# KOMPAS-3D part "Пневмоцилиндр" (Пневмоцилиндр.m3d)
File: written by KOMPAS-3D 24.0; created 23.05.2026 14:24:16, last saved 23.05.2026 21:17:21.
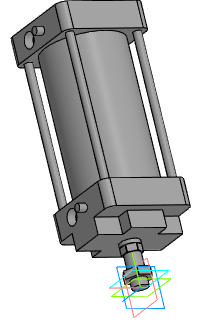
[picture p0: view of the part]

Document properties: Автор: R2D2; Полное имя файла: E:\Работа\Зайцев\GVKR1331E-1W-Fb-2P Задвижка шиберная DN.ru Ду50-300 Ру16-10-6\исходные материалы\DN100\Пневмоцилиндр.m3d

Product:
- Part/product: Пневмоцилиндр
    Масса: 19.177764

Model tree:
1. Эскиз:1
2. Элемент выдавливания:1
3. Смещенная плоскость:1
4. Эскиз:2
5. Элемент выдавливания:2
6. Эскиз:3  (with: Грань.Элемент выдавливания:1)
7. Элемент выдавливания:3
8. Эскиз:4  (with: Грань.Элемент выдавливания:3)
9. Элемент выдавливания:4  (with: Грань.Элемент выдавливания:3)
     Расстояние 2 = 9; Смещение 2 = 5
10. Эскиз:5  (with: Грань.Элемент выдавливания:3)
11. Элемент выдавливания:5
12. Эскиз:6  (with: Грань.Элемент выдавливания:5)
13. Элемент выдавливания:6
14. Эскиз:7  (with: Грань.Элемент выдавливания:6)
15. Элемент выдавливания:7
16. Эскиз:8  (with: Грань.Элемент выдавливания:7, Ребро.Элемент выдавливания:6)
17. Элемент выдавливания:8
18. Эскиз:9  (with: Грань.Элемент выдавливания:6, Вершина.Элемент выдавливания:8)
19. Элемент выдавливания:9  (with: Грань.Элемент выдавливания:8)
     Расстояние 1 = 178
20. Массив по концентрической сетке:1  (with: Элемент выдавливания:9, Эскиз:9)  (4 pattern instances)
     Шаг 2 = 360
21. Скругление:1  (with: Ребро.Элемент выдавливания:6, Ребро.Элемент выдавливания:8)
     Радиус = 10
22. Эскиз:10  (with: Грань.Элемент выдавливания:5, Ребро.Элемент выдавливания:6, Ребро.Элемент выдавливания:8)
23. Элемент выдавливания:10
24. Эскиз:11  (with: Грань.Элемент выдавливания:5, Ребро.Элемент выдавливания:10)
25. Элемент выдавливания:11
26. Эскиз:12  (with: Ребро.Элемент выдавливания:6, Ребро.Элемент выдавливания:5)
27. Элемент выдавливания:12

Expressions: k/2; c-2*g+x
